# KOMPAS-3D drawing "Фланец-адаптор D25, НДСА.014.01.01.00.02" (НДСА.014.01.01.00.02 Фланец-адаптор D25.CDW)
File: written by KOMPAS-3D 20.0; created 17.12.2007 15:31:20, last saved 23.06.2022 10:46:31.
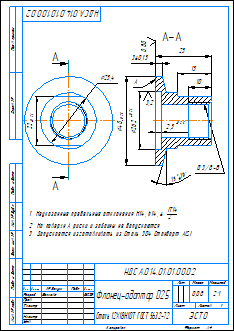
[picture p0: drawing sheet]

Sheet 1: A4, portrait

Document properties: Полное имя файла: C:\Users\cherbakova\Desktop\PLM\НДСА.014.01.01.00.02 Фланец-адаптор D25.CDW; Автор: Ширяева О.А.; Организация: Эсто-вакуум; 232338974461: <item xmlns="http://appius.ru/pdm" xmlns:xs="http://www.w3.org/2001/XMLSchema" xmlns:xsi="http://www.w3.org/2001/XMLSchema-instance" xsi:type="item">  <element xmlns:d2p1="http://v8.1c.ru/8.1/data/enterprise/current-config" xsi:type="d2p1:CatalogRef.aps_Элемен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; PLM_CDWXDTO: <item xmlns="http://appius.ru/pdm" xmlns:xs="http://www.w3.org/2001/XMLSchema" xmlns:xsi="http://www.w3.org/2001/XMLSchema-instance" xsi:type="item">  <element xmlns:d2p1="http://v8.1c.ru/8.1/data/enterprise/current-config" xsi:type="d2p1:CatalogRef.aps_Элемен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; Масса: 0.0774996

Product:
- Part/product: Фланец-адаптор D25  | designation НДСА.014.01.01.00.02
    Материал: Сталь 12Х18Н10Т ГОСТ 5632-72 (density 7900 kg/m3)
    Масса: 0.0774996

Title block, sheet 1: Наименование: Фланец-адаптор D25; designation: НДСА.014.01.01.00.02; Материал: Сталь 12Х18Н10Т ГОСТ 5632-72; Масса: 0,08; scale: 2:1; Количество листов документа: 1; organisation: ЭСТО; Форматы листов документа: A4; stored path: D:\Work-Kompas\Копир\УКРД.775.01.00.00.28 Флднец-адаптор D25.cdw; Разработал: Волкова; Разработал, date: 06.12.2019
Table, sheet 1:
  0^Material:V27FFD6AC31654437822AAF34B18F4E49

Views: Вид 1, Справа, Разрез А-А
Referenced files in C:\Users\Конструктор 1\Desktop\Система вакуумная криогенная\: НДСА.014.01.01.00.02 Фланец-адаптор D25.m3d
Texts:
  Лит-Масса-Масштаб
  Материал-Предприятие
  НДСА.014.01.01.00.02 Фланец-адаптор D25
Dimensions and other numbers on the sheet: 22; 25,4; 40; 26,2; 3,2; 3±0,15; 2,5; 0,80; 25; 15; 10; 2:1; 1; 0,08; 06.12.2019

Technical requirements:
  Неуказанные предельные отклонения H14, h14,    IT14 2 .
  На поверхн.А риски и забоины не допускаются.
  Допускается изготавливать из Сталь 304 Стандарт AISI.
